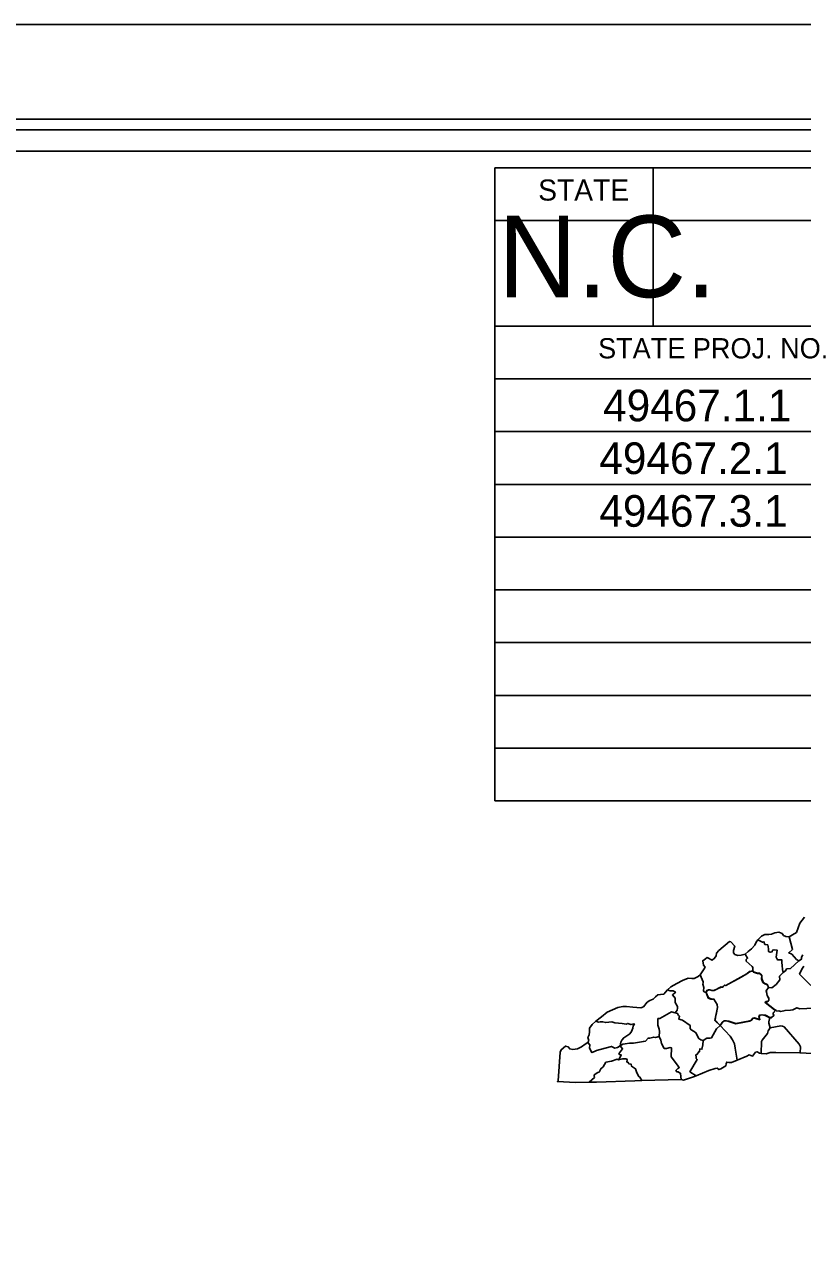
# Model space of a CAD drawing. Extents: x 925297 to 940193, y 663541 to 689899.
# Drawn here: x 935468 to 936944, y 687580 to 689899 of the extents above; entities that cross this region are included whole.
import ezdxf

# ---------------------------------------------------------------- set-up
doc = ezdxf.new("R2010")
doc.units = 0
for name, color, linetype in [('Exist Horizontal Alignment Tick Large', 7, 'Continuous'), ('Old_Level_20', 7, 'Continuous'), ('Sheet Cutting Line CELL', 7, 'Continuous'), ('Sheet Data Field CELL', 7, 'Continuous'), ('Sheet Plot Border Inside CELL', 7, 'Continuous'), ('Sheet Plot Border Outside CELL', 7, 'Continuous'), ('Sheet Title CELL', 7, 'Continuous')]:
    doc.layers.add(name, color=color, linetype=linetype)

msp = doc.modelspace()

# ---------------------------------------------------------------- linework, layer by layer
at = {"layer": 'Exist Horizontal Alignment Tick Large'}
msp.add_lwpolyline([(936893.4, 688029.5), (936888.2, 688024.1), (936888.2, 688022.2), (936889.5, 688019.5), (936885.1, 688015.4), (936881.7, 688015.3), (936873.4, 688019.7), (936867.1, 688020.8), (936862.6, 688020), (936861.3, 688016.9), (936862.4, 688014.5), (936862.8, 688011.5), (936852.7, 688014.7), (936849.8, 688014.5), (936846.9, 688010.8), (936843.9, 688009.2), (936817.5, 688003.8), (936804.2, 688008.5), (936799, 688009.4), (936795.4, 688009.3), (936791.4, 688006), (936787.6, 688000.4), (936778, 688010.1), (936782.8, 688034.8), (936782.1, 688040.4), (936775.9, 688050.5), (936770.3, 688050.6), (936765.3, 688052.6), (936761.3, 688063), (936762.6, 688066.7), (936765.3, 688067.8), (936767.8, 688068), (936771.8, 688066.9), (936776, 688067), (936789.7, 688073.5), (936792.5, 688073.2), (936795.8, 688076.9), (936798.5, 688076.3), (936838.3, 688098.5), (936843.3, 688102.6), (936849.3, 688103.7), (936850.8, 688101.9), (936858.3, 688099.3), (936862.7, 688099.2), (936865, 688097.6), (936866.9, 688095.1), (936866.4, 688089.1), (936868.9, 688082.4), (936872.2, 688079.8), (936875.9, 688078.5), (936877.5, 688077.5), (936879.3, 688072.6), (936874.8, 688066.3), (936875.7, 688064.2), (936876.7, 688057.5), (936879.9, 688051.8), (936880, 688048.3), (936877.7, 688045.8), (936874.9, 688045.6), (936873.1, 688044.5), (936890.7, 688030.6)], close=True, dxfattribs=at)
at = {"layer": 'Old_Level_20'}
for points in [[(936947.5, 688206.3), (936939.2, 688194.6), (936932.6, 688177.2), (936924.9, 688172.7), (936918.8, 688168.8), (936912.1, 688169.4), (936908.2, 688171.3), (936905.3, 688175.3), (936899.2, 688177.5), (936891.4, 688176.3), (936885.4, 688173.7), (936880.3, 688173.3), (936872.7, 688173.2), (936866.4, 688170.1), (936859, 688163.3), (936856, 688159), (936853.8, 688153.2), (936847.5, 688146.3), (936840.6, 688140.8), (936835.3, 688136.2), (936827.7, 688134.2), (936821.2, 688133.6), (936815.8, 688135.4), (936813.1, 688138.5), (936813.2, 688143.2), (936815.6, 688151.2), (936808, 688159.3), (936805.2, 688159.7), (936785.4, 688142.8), (936780.8, 688138.1), (936780.1, 688132.7), (936777.3, 688128.1), (936772.4, 688124.8), (936763.2, 688129.5), (936759.8, 688126.9), (936754.9, 688123.4), (936756.1, 688115.3), (936759.2, 688111.6), (936756.1, 688106.4), (936749.8, 688096.5), (936745.8, 688093.7)], [(936944.5, 688134.7), (936941.9, 688130.4), (936941.9, 688126.2), (936937, 688123.5), (936932.6, 688125.8), (936923.6, 688136.1), (936918, 688138.5), (936925, 688144.5), (936918.8, 688168.8), (936924.9, 688172.7), (936932.6, 688177.2), (936939.2, 688194.6), (936947.5, 688206.3)], [(936859, 688163.3), (936868.2, 688158.5), (936870.9, 688159.6), (936872.7, 688154.4), (936878.2, 688153.4), (936879.3, 688146.3), (936879.6, 688140.8), (936882.8, 688139.5), (936886.6, 688140.4), (936887.3, 688143.6), (936890.2, 688144.3), (936895.7, 688143.6), (936893.9, 688130.1), (936896.4, 688125.3), (936904.5, 688125.4), (936904.6, 688120.1), (936905.5, 688114.2), (936905.9, 688106.7), (936907.1, 688101), (936900.6, 688094.1), (936901, 688087.2), (936894, 688078.7), (936885.8, 688071.8), (936879.5, 688072.9), (936877.7, 688077.8), (936876.1, 688078.9), (936872.4, 688080.2), (936869.1, 688082.8), (936866.6, 688089.5), (936867.1, 688095.5), (936865.2, 688097.9), (936862.9, 688099.6), (936858.5, 688099.6), (936851, 688102.2), (936849.5, 688104.1), (936849.8, 688110.6), (936848.7, 688112.4), (936837.4, 688122.4), (936837.3, 688125.8), (936839.8, 688128.2), (936835.3, 688136.2), (936840.6, 688140.8), (936847.5, 688146.3), (936853.8, 688153.2), (936856, 688159), (936859, 688163.3)], [(936937, 688123.5), (936921, 688108.8), (936913.7, 688108.1), (936912.4, 688105), (936907.1, 688101), (936905.9, 688106.7), (936905.5, 688114.2), (936904.6, 688120.1), (936904.5, 688125.4), (936896.4, 688125.3), (936893.9, 688130.1), (936895.7, 688143.6), (936890.2, 688144.3), (936887.3, 688143.6), (936886.6, 688140.4), (936882.8, 688139.5), (936879.6, 688140.8), (936879.3, 688146.3), (936878.2, 688153.4), (936872.7, 688154.4), (936870.9, 688159.6), (936868.2, 688158.5), (936859, 688163.3), (936866.4, 688170.1), (936872.7, 688173.2), (936880.3, 688173.3), (936885.4, 688173.7), (936891.4, 688176.3), (936899.2, 688177.5), (936905.3, 688175.3), (936908.2, 688171.3), (936912.1, 688169.4), (936918.8, 688168.8), (936925, 688144.5), (936918, 688138.5), (936923.6, 688136.1), (936932.6, 688125.8), (936937, 688123.5)], [(936785.4, 688142.8), (936805.2, 688159.7), (936808, 688159.3), (936815.6, 688151.2), (936813.2, 688143.2), (936813.1, 688138.5), (936815.8, 688135.4), (936821.2, 688133.6), (936827.7, 688134.2), (936835.3, 688136.2), (936839.8, 688128.2), (936837.3, 688125.8), (936837.4, 688122.4), (936848.7, 688112.4), (936849.8, 688110.6), (936849.5, 688104.1), (936843.5, 688102.9), (936838.5, 688098.9), (936823.1, 688090.1), (936802.9, 688078.9), (936798.7, 688076.6), (936796, 688077.2), (936794.3, 688075.5), (936792.7, 688073.5), (936789.9, 688073.9), (936776.2, 688067.3), (936772.1, 688067.3), (936768, 688068.3), (936765.5, 688068.1), (936762.8, 688067.1), (936761.5, 688063.4), (936757.5, 688064.7), (936756, 688066.2), (936756.6, 688072.8), (936754.8, 688078.8), (936755.7, 688081.4), (936755.4, 688083.7), (936749.8, 688096.5), (936756.1, 688106.4), (936759.2, 688111.6), (936756.1, 688115.3), (936754.9, 688123.4), (936759.8, 688126.9), (936763.2, 688129.5), (936772.4, 688124.8), (936777.3, 688128.1), (936780.1, 688132.7), (936780.8, 688138.1), (936785.4, 688142.8)], [(936965.3, 688033.8), (936939.2, 688032.6), (936933.5, 688034.5), (936925.8, 688030.5), (936920.9, 688029.5), (936910.8, 688029.2), (936902.8, 688027.5), (936899, 688028.3), (936895, 688028), (936893.6, 688029.8), (936890.9, 688031), (936873.3, 688044.8), (936875.1, 688046), (936877.9, 688046.2), (936880.2, 688048.6), (936880.1, 688052.2), (936877, 688057.8), (936875.9, 688064.6), (936875.1, 688066.6), (936879.5, 688072.9), (936885.8, 688071.8), (936894, 688078.7), (936901, 688087.2), (936900.6, 688094.1), (936907.1, 688101), (936912.4, 688105), (936913.7, 688108.1), (936921, 688108.8), (936937, 688123.5), (936941.9, 688126.2), (936941.9, 688130.4)], [(936941.9, 688130.4), (936944.5, 688134.7)], [(936745.8, 688093.7), (936738.8, 688089.5), (936734.1, 688089.6), (936727.2, 688090.4), (936716.6, 688085.9), (936705.9, 688080.6), (936694.2, 688074.3), (936688.1, 688068.2), (936684.2, 688063.7), (936680.7, 688060.3), (936674.5, 688059.6), (936669.4, 688059.1), (936665.3, 688054.9), (936660.9, 688050.5), (936654.2, 688048.3), (936649.3, 688044.7), (936642.4, 688036.2), (936637.4, 688034.1), (936622, 688035.3), (936609.9, 688036.7), (936603.5, 688036.9), (936594, 688034.7), (936583.5, 688030.7), (936573.8, 688026), (936562.5, 688017.4), (936552.3, 688008.7), (936545.2, 688002.7), (936540, 687995.9), (936540.3, 687988.4), (936539.6, 687982.8), (936537.1, 687977.9), (936538.7, 687972.2), (936537.1, 687968.3), (936531.8, 687965.3), (936524.6, 687960.1), (936517.2, 687956.3), (936508.7, 687955), (936502.5, 687956.3), (936499.6, 687960.1), (936494.8, 687961.8), (936486.3, 687954.8), (936484.6, 687950), (936480.5, 687895.9), (936479.2, 687894.4), (936513.6, 687892.9), (936539.6, 687893.2), (936553.2, 687893.3), (936625.8, 687895.7), (936639.2, 687896.3), (936713.8, 687898), (936718.3, 687896.9), (936739.1, 687903.9), (936742.1, 687905.5), (936766.1, 687915.4), (936778.2, 687919.1), (936782.4, 687919.6), (936785.4, 687917.1), (936789.2, 687918.5), (936798.5, 687924.2), (936799.5, 687927.9), (936800.2, 687931.3), (936804.3, 687930.8), (936809.3, 687930.5), (936819.8, 687934.9), (936838.6, 687942.3), (936843.1, 687945), (936849.2, 687942.6), (936855.1, 687950.1), (936857.7, 687950.8), (936862.1, 687948.1), (936865.4, 687947.7), (936875, 687947), (936882.6, 687949.5), (936893.1, 687949.3), (936939.4, 687948.6), (936962.3, 687947.5)], [(936749.8, 688096.5), (936755.4, 688083.7), (936755.7, 688081.4), (936754.8, 688078.8), (936756.6, 688072.8), (936756, 688066.2), (936757.5, 688064.7), (936761.5, 688063.4), (936765.5, 688053), (936770.5, 688051), (936776.1, 688050.8), (936782.3, 688040.7), (936783, 688035.1), (936781.1, 688024.9), (936779.2, 688016.4), (936778.2, 688010.5), (936787.8, 688000.8), (936781.1, 687994.2), (936771.5, 687977.6), (936768.6, 687976.6), (936762.7, 687976.5), (936755.8, 687972.4), (936750.9, 687973.3), (936747.1, 687976), (936741.8, 687987), (936738.2, 687989.1), (936733.1, 687992.5), (936731.1, 687994.9), (936730.7, 688000.7), (936716.4, 688010.9), (936709.7, 688012.8), (936710.4, 688018.3), (936708.6, 688019.8), (936707.2, 688023.6), (936702.3, 688025), (936706, 688029.8), (936707, 688033.8), (936707.2, 688037), (936702.5, 688044.2), (936702.4, 688052.4), (936697.3, 688058.6), (936698.9, 688060.3), (936702.5, 688062.9), (936703, 688064.2), (936698.5, 688066.6), (936693.2, 688066.2), (936688.1, 688068.2), (936694.2, 688074.3), (936705.9, 688080.6), (936716.6, 688085.9), (936727.2, 688090.4), (936734.1, 688089.6), (936738.8, 688089.5), (936745.8, 688093.7), (936749.8, 688096.5)], [(936843.5, 688102.9), (936849.5, 688104.1), (936851, 688102.2), (936858.5, 688099.6), (936862.9, 688099.6), (936865.2, 688097.9), (936867.1, 688095.5), (936866.6, 688089.5), (936869.1, 688082.8), (936872.4, 688080.2), (936876.1, 688078.9), (936877.7, 688077.8), (936879.5, 688072.9), (936875.1, 688066.6), (936875.9, 688064.6), (936877, 688057.8), (936880.1, 688052.2), (936880.2, 688048.6), (936877.9, 688046.2), (936875.1, 688046), (936873.3, 688044.8), (936890.9, 688031), (936893.6, 688029.8), (936888.4, 688024.5), (936888.4, 688022.5), (936889.7, 688019.9), (936885.3, 688015.8), (936881.9, 688015.7), (936873.6, 688020.1), (936867.3, 688021.1), (936862.8, 688020.4), (936861.5, 688017.2), (936862.6, 688014.9), (936863, 688011.8), (936852.9, 688015), (936850.1, 688014.9), (936847.1, 688011.1), (936844.1, 688009.6), (936817.7, 688004.2), (936804.4, 688008.9), (936799.3, 688009.8), (936795.6, 688009.7), (936791.6, 688006.4), (936787.8, 688000.8), (936778.2, 688010.5), (936779.2, 688016.4), (936781.1, 688024.9), (936783, 688035.1), (936782.3, 688040.7), (936776.1, 688050.8), (936770.5, 688051), (936765.5, 688053), (936761.5, 688063.4), (936762.8, 688067.1), (936765.5, 688068.1), (936768, 688068.3), (936772.1, 688067.3), (936776.2, 688067.3), (936789.9, 688073.9), (936792.7, 688073.5), (936794.3, 688075.5), (936796, 688077.2), (936798.7, 688076.6), (936802.9, 688078.9), (936823.1, 688090.1), (936838.5, 688098.9), (936843.5, 688102.9)], [(936960, 688076.3), (936938.4, 688098.3), (936942.7, 688107.3), (936946.5, 688112.9)], [(936946.5, 688112.9), (936942.7, 688107.3), (936938.4, 688098.3), (936960, 688076.3)], [(936624.6, 688004), (936618.6, 688002.5), (936612.5, 688004.6), (936609.5, 688003), (936602.1, 688004.2), (936588.2, 688006), (936582.3, 688007.8), (936570.7, 688006.1), (936565.3, 688007.5), (936560.3, 688007.6), (936556.9, 688007.1), (936552.3, 688008.7), (936562.5, 688017.4), (936573.8, 688026), (936583.5, 688030.7), (936594, 688034.7), (936603.5, 688036.9), (936609.9, 688036.7), (936622, 688035.3), (936637.4, 688034.1), (936642.4, 688036.2), (936649.3, 688044.7), (936654.2, 688048.3), (936660.9, 688050.5), (936665.3, 688054.9), (936669.4, 688059.1), (936674.5, 688059.6), (936680.7, 688060.3), (936684.2, 688063.7), (936688.1, 688068.2), (936693.2, 688066.2), (936698.5, 688066.6), (936703, 688064.2), (936702.5, 688062.9), (936698.9, 688060.3), (936697.3, 688058.6), (936702.4, 688052.4), (936702.5, 688044.2), (936707.2, 688037), (936707, 688033.8), (936706, 688029.8), (936702.3, 688025), (936695.5, 688026.4), (936673.7, 688014.1), (936669.8, 688013.8), (936669.7, 688001.5), (936672.1, 687993.8), (936672.9, 687989.3), (936672, 687980.1), (936665.4, 687978.1), (936661.9, 687978.6), (936654.7, 687976.9), (936651.1, 687976.8), (936645.9, 687970.9), (936642.3, 687970.5), (936623.6, 687967.2), (936616.1, 687967.5), (936607.9, 687966), (936603.1, 687965.5), (936598.2, 687961.9), (936599.4, 687969.4), (936601.5, 687972.8), (936605.1, 687977.5), (936610.5, 687981), (936616.5, 687985), (936619.5, 687989.3), (936622.5, 687995.5), (936623, 687999.8), (936625.1, 688003.4), (936624.6, 688004)], [(936695.5, 688026.4), (936702.3, 688025), (936707.2, 688023.6), (936708.6, 688019.8), (936710.4, 688018.3), (936709.7, 688012.8), (936716.4, 688010.9), (936730.7, 688000.7), (936731.1, 687994.9), (936733.1, 687992.5), (936738.2, 687989.1), (936741.8, 687987), (936747.1, 687976), (936750.9, 687973.3), (936755.8, 687972.4), (936755.1, 687964.3), (936753.2, 687955.8), (936749.1, 687956.3), (936748.7, 687951.1), (936747.3, 687950.8), (936744.5, 687946.2), (936741.5, 687944.6), (936742.4, 687941), (936742.3, 687938.2), (936744.3, 687936.1), (936730.6, 687912.9), (936742.1, 687905.5), (936739.1, 687903.9), (936718.3, 687896.9), (936713.8, 687898), (936712.8, 687909.9), (936708.4, 687912.6), (936705.4, 687913), (936704, 687915.3), (936707.3, 687919), (936710.2, 687920.6), (936708.6, 687923), (936694.8, 687941.6), (936695.5, 687958.4), (936693.3, 687958.9), (936685.9, 687957.1), (936681.8, 687957.3), (936676.8, 687966.7), (936675.4, 687973.1), (936672, 687980.1), (936672.9, 687989.3), (936672.1, 687993.8), (936669.7, 688001.5), (936669.8, 688013.8), (936673.7, 688014.1), (936695.5, 688026.4)], [(936962.3, 687947.5), (936939.4, 687948.6), (936940.1, 687960.3), (936937.5, 687965.6), (936909.1, 687998.4), (936906, 687999.6), (936903, 688000), (936882.7, 687996.4), (936879.9, 688005), (936879.8, 688007.7), (936881.9, 688015.7), (936885.3, 688015.8), (936889.7, 688019.9), (936888.4, 688022.5), (936888.4, 688024.5), (936893.6, 688029.8), (936895, 688028), (936899, 688028.3), (936902.8, 688027.5), (936910.8, 688029.2), (936920.9, 688029.5), (936925.8, 688030.5), (936933.5, 688034.5), (936939.2, 688032.6), (936965.3, 688033.8)], [(936598.2, 687961.9), (936592.9, 687958.7), (936588, 687957.6), (936581.5, 687961.1), (936560.3, 687955.3), (936553.4, 687953.1), (936549.6, 687951.3), (936544.7, 687949.4), (936540.1, 687957.6), (936540.5, 687963.8), (936537.1, 687968.3), (936538.7, 687972.2), (936537.1, 687977.9), (936539.6, 687982.8), (936540.3, 687988.4), (936540, 687995.9), (936545.2, 688002.7), (936552.3, 688008.7), (936556.9, 688007.1), (936560.3, 688007.6), (936565.3, 688007.5), (936570.7, 688006.1), (936582.3, 688007.8), (936588.2, 688006), (936602.1, 688004.2), (936609.5, 688003), (936612.5, 688004.6), (936618.6, 688002.5), (936624.6, 688004), (936625.1, 688003.4), (936623, 687999.8), (936622.5, 687995.5), (936619.5, 687989.3), (936616.5, 687985), (936610.5, 687981), (936605.1, 687977.5), (936601.5, 687972.8), (936599.4, 687969.4), (936598.2, 687961.9)], [(936787.8, 688000.8), (936806.9, 687980.3), (936811.5, 687973.4), (936815, 687965.9), (936816.4, 687957.7), (936819.8, 687934.9), (936809.3, 687930.5), (936804.3, 687930.8), (936800.2, 687931.3), (936799.5, 687927.9), (936798.5, 687924.2), (936789.2, 687918.5), (936785.4, 687917.1), (936782.4, 687919.6), (936778.2, 687919.1), (936766.1, 687915.4), (936742.1, 687905.5), (936730.6, 687912.9), (936744.3, 687936.1), (936742.3, 687938.2), (936742.4, 687941), (936741.5, 687944.6), (936744.5, 687946.2), (936747.3, 687950.8), (936748.7, 687951.1), (936749.1, 687956.3), (936753.2, 687955.8), (936755.1, 687964.3), (936755.8, 687972.4), (936762.7, 687976.5), (936768.6, 687976.6), (936771.5, 687977.6), (936781.1, 687994.2), (936787.8, 688000.8)], [(936882.7, 687996.4), (936878.8, 687990.3), (936877.3, 687985.5), (936867.6, 687972.8), (936866.4, 687970.2), (936865.4, 687947.7), (936862.1, 687948.1), (936857.7, 687950.8), (936855.1, 687950.1), (936849.2, 687942.6), (936843.1, 687945), (936838.6, 687942.3), (936819.8, 687934.9), (936816.4, 687957.7), (936815, 687965.9), (936811.5, 687973.4), (936806.9, 687980.3), (936787.8, 688000.8), (936791.6, 688006.4), (936795.6, 688009.7), (936799.3, 688009.8), (936804.4, 688008.9), (936817.7, 688004.2), (936844.1, 688009.6), (936847.1, 688011.1), (936850.1, 688014.9), (936852.9, 688015), (936863, 688011.8), (936862.6, 688014.9), (936861.5, 688017.2), (936862.8, 688020.4), (936867.3, 688021.1), (936873.6, 688020.1), (936881.9, 688015.7), (936879.8, 688007.7), (936879.9, 688005), (936882.7, 687996.4)], [(936882.7, 687996.4), (936903, 688000), (936906, 687999.6), (936909.1, 687998.4), (936937.5, 687965.6), (936940.1, 687960.3), (936939.4, 687948.6), (936893.1, 687949.3), (936882.6, 687949.5), (936875, 687947), (936865.4, 687947.7), (936866.4, 687970.2), (936867.6, 687972.8), (936877.3, 687985.5), (936878.8, 687990.3), (936882.7, 687996.4)], [(936665.4, 687978.1), (936672, 687980.1), (936675.4, 687973.1), (936676.8, 687966.7), (936681.8, 687957.3), (936685.9, 687957.1), (936693.3, 687958.9), (936695.5, 687958.4), (936694.8, 687941.6), (936708.6, 687923), (936710.2, 687920.6), (936707.3, 687919), (936704, 687915.3), (936705.4, 687913), (936708.4, 687912.6), (936712.8, 687909.9), (936713.8, 687898), (936639.2, 687896.3), (936635.6, 687903), (936633.5, 687904), (936629.6, 687910.8), (936627.5, 687918.7), (936619.7, 687923.4), (936618.8, 687927.6), (936614.8, 687928.3), (936613.6, 687930.4), (936610.5, 687931.5), (936611.2, 687935.6), (936610.1, 687937.6), (936602.8, 687937.3), (936595.2, 687935.8), (936597.9, 687940.4), (936600.1, 687944.8), (936597.2, 687945.6), (936595.9, 687946.6), (936597, 687948.7), (936602.6, 687956.5), (936598.2, 687961.9), (936603.1, 687965.5), (936607.9, 687966), (936616.1, 687967.5), (936623.6, 687967.2), (936642.3, 687970.5), (936645.9, 687970.9), (936651.1, 687976.8), (936654.7, 687976.9), (936661.9, 687978.6), (936665.4, 687978.1)], [(936598.2, 687961.9), (936602.6, 687956.5), (936597, 687948.7), (936595.9, 687946.6), (936597.2, 687945.6), (936600.1, 687944.8), (936597.9, 687940.4), (936595.2, 687935.8), (936592.3, 687936.9), (936581.6, 687933.2), (936571.1, 687931.1), (936565.9, 687922.4), (936561.6, 687918.8), (936558.1, 687912.4), (936555.8, 687911.6), (936548.9, 687906.9), (936549, 687905.5), (936549.2, 687902.2), (936539.6, 687893.2), (936513.6, 687892.9), (936479.2, 687894.4), (936480.5, 687895.9), (936484.6, 687950), (936486.3, 687954.8), (936494.8, 687961.8), (936499.6, 687960.1), (936502.5, 687956.3), (936508.7, 687955), (936517.2, 687956.3), (936524.6, 687960.1), (936531.8, 687965.3), (936537.1, 687968.3), (936540.5, 687963.8), (936540.1, 687957.6), (936544.7, 687949.4), (936549.6, 687951.3), (936553.4, 687953.1), (936560.3, 687955.3), (936581.5, 687961.1), (936588, 687957.6), (936592.9, 687958.7), (936598.2, 687961.9)], [(936610.1, 687937.6), (936611.2, 687935.6), (936610.5, 687931.5), (936613.6, 687930.4), (936614.8, 687928.3), (936618.8, 687927.6), (936619.7, 687923.4), (936627.5, 687918.7), (936629.6, 687910.8), (936633.5, 687904), (936635.6, 687903), (936639.2, 687896.3), (936625.8, 687895.7), (936553.2, 687893.3), (936539.6, 687893.2), (936549.2, 687902.2), (936549, 687905.5), (936548.9, 687906.9), (936555.8, 687911.6), (936558.1, 687912.4), (936561.6, 687918.8), (936565.9, 687922.4), (936571.1, 687931.1), (936581.6, 687933.2), (936592.3, 687936.9), (936595.2, 687935.8), (936602.8, 687937.3), (936610.1, 687937.6)], [(936789.2, 687918.5), (936785.4, 687917.1), (936782.4, 687919.6), (936778.2, 687919.1), (936766.1, 687915.4), (936742.1, 687905.5), (936739.1, 687903.9)]]:
    msp.add_lwpolyline(points, dxfattribs=at)
at = {"layer": 'Sheet Cutting Line CELL'}
msp.add_line((925296.7, 689898.6), (938768.7, 689898.6), dxfattribs=at)
at = {"layer": 'Sheet Plot Border Inside CELL'}
msp.add_lwpolyline([(925400.7, 681278.2), (938732.7, 681278.2), (938732.7, 689719), (925400.7, 689719)], close=True, dxfattribs=at)
at = {"layer": 'Sheet Plot Border Outside CELL'}
msp.add_lwpolyline([(938768.7, 689898.6), (925296.7, 689898.6), (925296.7, 681098.7), (938768.7, 681098.7)], close=True, dxfattribs=at)
at = {"layer": 'Sheet Title CELL'}
for points in [[(938552.8, 689698.6), (926712.6, 689698.7)], [(938512.7, 689658.6), (927152.8, 689658.6)], [(938560.7, 689626.7), (936360.7, 689626.6), (936360.7, 688426.7), (937093.9, 688426.6)], [(937093.9, 689326.6), (936660.7, 689326.6), (936660.7, 689626.7), (937960.8, 689626.6)], [(938560.7, 689326.7), (936360.7, 689326.7), (936360.7, 689526.7), (938560.7, 689526.7)], [(938560.7, 689126.6), (936360.7, 689126.6), (936360.7, 689226.6), (938560.7, 689226.6)], [(938560.7, 688926.7), (936360.7, 688926.7), (936360.7, 689026.6), (938560.7, 689026.7)], [(938560.7, 688726.6), (936360.8, 688726.6), (936360.7, 688826.7), (938560.7, 688826.7)], [(938560.7, 688526.6), (936360.7, 688526.7), (936360.7, 688626.6), (938560.7, 688626.6)], [(936360.7, 688426.7), (938560.7, 688426.7)]]:
    msp.add_lwpolyline(points, dxfattribs=at)

# ---------------------------------------------------------------- texts
at = {"layer": 'Sheet Data Field CELL'}
for s, p in [('49467.1.1', (936565.9, 689146.2)), ('49467.2.1', (936558.7, 689046.2)), ('49467.3.1', (936558.7, 688946.3))]:
    msp.add_text(s, height=60, dxfattribs=at).set_placement(p)
at = {"layer": 'Sheet Title CELL'}
for s, height, p in [('STATE', 40, (936442.7, 689564.7)), ('N.C.', 154.8, (936366.7, 689381.5)), ('STATE PROJ. NO.', 38.4, (936556.3, 689265.5))]:
    msp.add_text(s, height=height, rotation=360, dxfattribs=at).set_placement(p)

doc.saveas('drawing.dxf')
